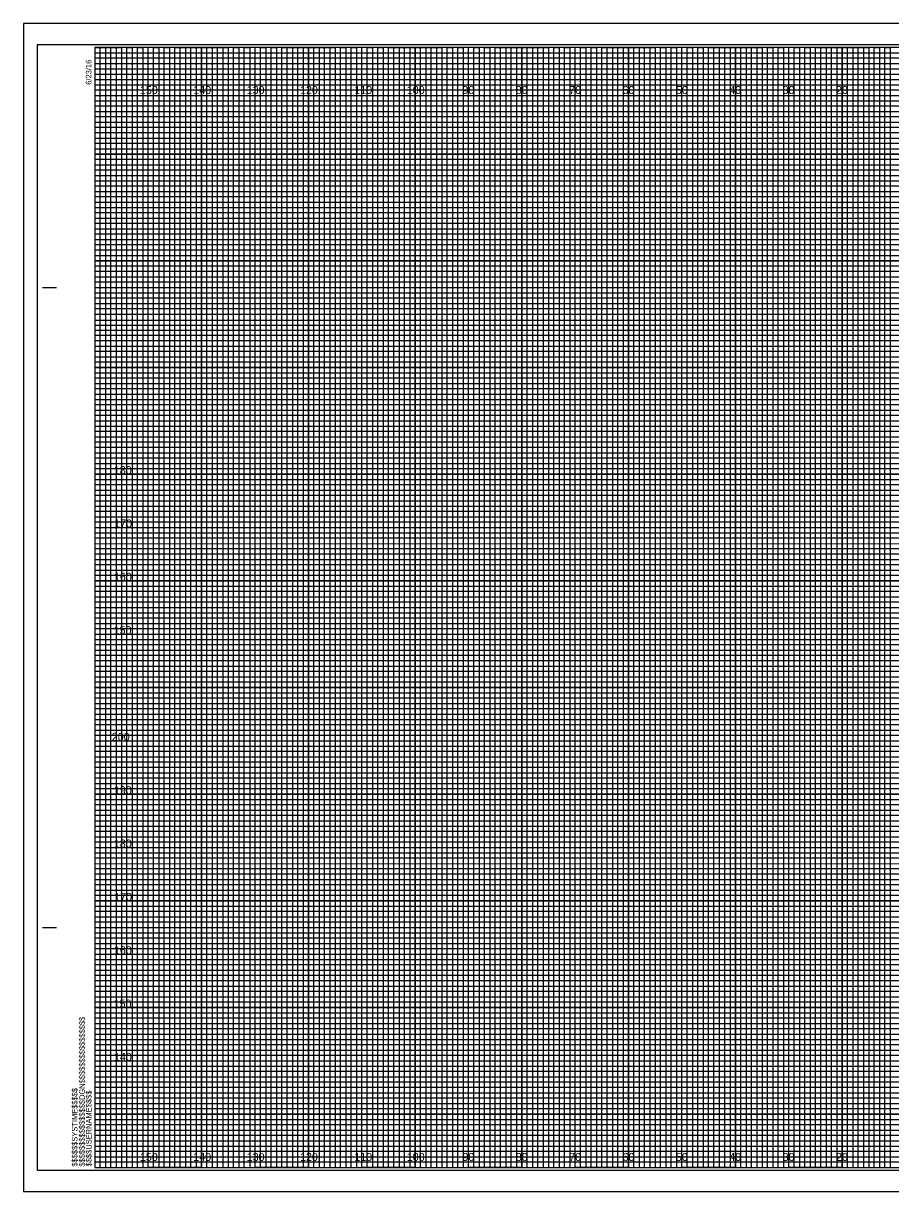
# Model space of a CAD drawing. Extents: x -13 to 323, y -5 to 4174.
# Drawn here: x -13.4 to 149.1, y 3295.5 to 3514.5 of the extents above; entities that cross this region are included whole.
import ezdxf

# ---------------------------------------------------------------- set-up
doc = ezdxf.new("R2010")
doc.units = 0
for name, color, linetype in [('Exist Cross Section Cell', 7, 'Continuous'), ('Exist XS Center Line Elevation Label', 7, 'Continuous'), ('Exist XS Ground Line', 7, 'Continuous'), ('Prop CMT Guardrail Graphics', 7, 'Continuous'), ('Prop CMT Pvmt Course 1', 7, 'Continuous'), ('Prop CMT Pvmt Course 2', 7, 'Continuous'), ('Prop CMT Pvmt Course 3', 7, 'Continuous'), ('Prop CMT Shld Paved Course 1', 7, 'Continuous'), ('Prop CMT Shld Paved Course 2', 7, 'Continuous'), ('Prop CMT Subgrade Earthwork', 7, 'Continuous'), ('Scratch_Level_0', 7, 'Continuous')]:
    doc.layers.add(name, color=color, linetype=linetype)

msp = doc.modelspace()

# ---------------------------------------------------------------- linework, layer by layer
at = {"layer": 'Exist XS Center Line Elevation Label'}
for points in [[(0, 3510), (5, 3510), (5, 3300), (15, 3300), (15, 3510), (25, 3510), (25, 3300), (35, 3300), (35, 3510), (45, 3510), (45, 3300), (55, 3300), (55, 3510), (65, 3510), (65, 3300), (75, 3300), (75, 3510), (85, 3510), (85, 3300), (95, 3300), (95, 3510), (105, 3510), (105, 3300), (115, 3300), (115, 3510), (125, 3510), (125, 3300), (135, 3300), (135, 3510), (145, 3510), (145, 3300), (155, 3300)], [(0, 3505), (275, 3505)], [(0, 3485), (320, 3485), (320, 3495), (0, 3495)], [(0, 3465), (320, 3465), (320, 3475), (0, 3475)], [(0, 3445), (320, 3445), (320, 3455), (0, 3455)], [(0, 3425), (320, 3425), (320, 3435), (0, 3435)], [(0, 3405), (320, 3405), (320, 3415), (0, 3415)], [(0, 3385), (320, 3385), (320, 3395), (0, 3395)], [(0, 3365), (320, 3365), (320, 3375), (0, 3375)], [(0, 3345), (320, 3345), (320, 3355), (0, 3355)], [(0, 3325), (320, 3325), (320, 3335), (0, 3335)], [(0, 3305), (320, 3305), (320, 3315), (0, 3315)]]:
    msp.add_lwpolyline(points, dxfattribs=at)
at = {"layer": 'Exist XS Ground Line'}
for p, q in [((10, 3510), (0, 3510)), ((10, 3300), (10, 3510)), ((30, 3510), (20, 3510)), ((20, 3510), (20, 3300)), ((30, 3300), (30, 3510)), ((50, 3510), (40, 3510)), ((40, 3510), (40, 3300)), ((50, 3300), (50, 3510)), ((70, 3510), (60, 3510)), ((60, 3510), (60, 3300)), ((70, 3300), (70, 3510)), ((90, 3510), (80, 3510)), ((80, 3510), (80, 3300)), ((90, 3300), (90, 3510)), ((110, 3510), (100, 3510)), ((100, 3510), (100, 3300)), ((110, 3300), (110, 3510)), ((130, 3510), (120, 3510)), ((120, 3510), (120, 3300)), ((130, 3300), (130, 3510)), ((150, 3510), (140, 3510)), ((140, 3510), (140, 3300)), ((20, 3300), (10, 3300)), ((40, 3300), (30, 3300)), ((60, 3300), (50, 3300)), ((80, 3300), (70, 3300)), ((100, 3300), (90, 3300)), ((120, 3300), (110, 3300)), ((140, 3300), (130, 3300))]:
    msp.add_line(p, q, dxfattribs=at)
for points in [[(0, 3500), (320, 3500), (320, 3490), (0, 3490)], [(0, 3480), (320, 3480), (320, 3470), (0, 3470)], [(0, 3460), (320, 3460), (320, 3450), (0, 3450)], [(0, 3440), (320, 3440), (320, 3430), (0, 3430)], [(0, 3420), (320, 3420), (320, 3410), (0, 3410)], [(0, 3400), (320, 3400), (320, 3390), (0, 3390)], [(0, 3380), (320, 3380), (320, 3370), (0, 3370)], [(0, 3360), (320, 3360), (320, 3350), (0, 3350)], [(0, 3340), (320, 3340), (320, 3330), (0, 3330)], [(0, 3320), (320, 3320), (320, 3310), (0, 3310)]]:
    msp.add_lwpolyline(points, dxfattribs=at)
at = {"layer": 'Prop CMT Pvmt Course 1'}
for p, q in [((323.3, 3514.5), (-13.4, 3514.5)), ((-13.4, 3514.5), (-13.4, 3295.5)), ((-13.4, 3295.5), (323.3, 3295.5))]:
    msp.add_line(p, q, dxfattribs=at)
at = {"layer": 'Prop CMT Pvmt Course 2'}
msp.add_lwpolyline([(-13.4, 3295.5), (323.3, 3295.5), (323.3, 3514.5), (-13.4, 3514.5)], close=True, dxfattribs=at)
at = {"layer": 'Prop CMT Pvmt Course 3'}
msp.add_lwpolyline([(-10.8, 3299.5), (322.4, 3299.5), (322.4, 3510.5), (-10.8, 3510.5)], close=True, dxfattribs=at)
at = {"layer": 'Prop CMT Shld Paved Course 1'}
for p, q in [((-9.8, 3465), (-7.3, 3465)), ((-9.7, 3465), (-7.2, 3465)), ((-9.8, 3345), (-7.3, 3345)), ((-9.7, 3345), (-7.2, 3345)), ((0, 3300), (0, 3300)), ((0, 3300), (0, 3300)), ((0, 3300), (0, 3300)), ((0, 3300), (0, 3300)), ((0, 3300), (0, 3300)), ((0, 3300), (0, 3300)), ((0, 3300), (0, 3300))]:
    msp.add_line(p, q, dxfattribs=at)
msp.add_lwpolyline([(320, 3510), (0, 3510), (0, 3300), (320, 3300)], close=True, dxfattribs=at)
at = {"layer": 'Prop CMT Shld Paved Course 2'}
for points in [[(0, 3300), (1, 3300), (1, 3510), (2, 3510), (2, 3300)], [(2, 3300), (3, 3300), (3, 3510), (4, 3510), (4, 3300)], [(5, 3300), (6, 3300), (6, 3510), (7, 3510), (7, 3300)], [(7, 3300), (8, 3300), (8, 3510), (9, 3510), (9, 3300)], [(10, 3300), (11, 3300), (11, 3510), (12, 3510), (12, 3300)], [(12, 3300), (13, 3300), (13, 3510), (14, 3510), (14, 3300)], [(15, 3300), (16, 3300), (16, 3510), (17, 3510), (17, 3300)], [(17, 3300), (18, 3300), (18, 3510), (19, 3510), (19, 3300)], [(20, 3300), (21, 3300), (21, 3510), (22, 3510), (22, 3300)], [(22, 3300), (23, 3300), (23, 3510), (24, 3510), (24, 3300)], [(25, 3300), (26, 3300), (26, 3510), (27, 3510), (27, 3300)], [(27, 3300), (28, 3300), (28, 3510), (29, 3510), (29, 3300)], [(30, 3300), (31, 3300), (31, 3510), (32, 3510), (32, 3300)], [(32, 3300), (33, 3300), (33, 3510), (34, 3510), (34, 3300)], [(35, 3300), (36, 3300), (36, 3510), (37, 3510), (37, 3300)], [(37, 3300), (38, 3300), (38, 3510), (39, 3510), (39, 3300)], [(40, 3300), (41, 3300), (41, 3510), (42, 3510), (42, 3300)], [(42, 3300), (43, 3300), (43, 3510), (44, 3510), (44, 3300)], [(45, 3300), (46, 3300), (46, 3510), (47, 3510), (47, 3300)], [(47, 3300), (48, 3300), (48, 3510), (49, 3510), (49, 3300)], [(50, 3300), (51, 3300), (51, 3510), (52, 3510), (52, 3300)], [(52, 3300), (53, 3300), (53, 3510), (54, 3510), (54, 3300)], [(55, 3300), (56, 3300), (56, 3510), (57, 3510), (57, 3300)], [(57, 3300), (58, 3300), (58, 3510), (59, 3510), (59, 3300)], [(60, 3300), (61, 3300), (61, 3510), (62, 3510), (62, 3300)], [(62, 3300), (63, 3300), (63, 3510), (64, 3510), (64, 3300)], [(65, 3300), (66, 3300), (66, 3510), (67, 3510), (67, 3300)], [(67, 3300), (68, 3300), (68, 3510), (69, 3510), (69, 3300)], [(70, 3300), (71, 3300), (71, 3510), (72, 3510), (72, 3300)], [(72, 3300), (73, 3300), (73, 3510), (74, 3510), (74, 3300)], [(75, 3300), (76, 3300), (76, 3510), (77, 3510), (77, 3300)], [(77, 3300), (78, 3300), (78, 3510), (79, 3510), (79, 3300)], [(80, 3300), (81, 3300), (81, 3510), (82, 3510), (82, 3300)], [(82, 3300), (83, 3300), (83, 3510), (84, 3510), (84, 3300)], [(85, 3300), (86, 3300), (86, 3510), (87, 3510), (87, 3300)], [(87, 3300), (88, 3300), (88, 3510), (89, 3510), (89, 3300)], [(90, 3300), (91, 3300), (91, 3510), (92, 3510), (92, 3300)], [(92, 3300), (93, 3300), (93, 3510), (94, 3510), (94, 3300)], [(95, 3300), (96, 3300), (96, 3510), (97, 3510), (97, 3300)], [(97, 3300), (98, 3300), (98, 3510), (99, 3510), (99, 3300)], [(100, 3300), (101, 3300), (101, 3510), (102, 3510), (102, 3300)], [(102, 3300), (103, 3300), (103, 3510), (104, 3510), (104, 3300)], [(105, 3300), (106, 3300), (106, 3510), (107, 3510), (107, 3300)], [(107, 3300), (108, 3300), (108, 3510), (109, 3510), (109, 3300)], [(110, 3300), (111, 3300), (111, 3510), (112, 3510), (112, 3300)], [(112, 3300), (113, 3300), (113, 3510), (114, 3510), (114, 3300)], [(115, 3300), (116, 3300), (116, 3510), (117, 3510), (117, 3300)], [(117, 3300), (118, 3300), (118, 3510), (119, 3510), (119, 3300)], [(120, 3300), (121, 3300), (121, 3510), (122, 3510), (122, 3300)], [(122, 3300), (123, 3300), (123, 3510), (124, 3510), (124, 3300)], [(125, 3300), (126, 3300), (126, 3510), (127, 3510), (127, 3300)], [(127, 3300), (128, 3300), (128, 3510), (129, 3510), (129, 3300)], [(130, 3300), (131, 3300), (131, 3510), (132, 3510), (132, 3300)], [(132, 3300), (133, 3300), (133, 3510), (134, 3510), (134, 3300)], [(135, 3300), (136, 3300), (136, 3510), (137, 3510), (137, 3300)], [(137, 3300), (138, 3300), (138, 3510), (139, 3510), (139, 3300)], [(140, 3300), (141, 3300), (141, 3510), (142, 3510), (142, 3300)], [(142, 3300), (143, 3300), (143, 3510), (144, 3510), (144, 3300)], [(145, 3300), (146, 3300), (146, 3510), (147, 3510), (147, 3300)], [(147, 3300), (148, 3300), (148, 3510), (149, 3510), (149, 3300)]]:
    msp.add_lwpolyline(points, dxfattribs=at)
at = {"layer": 'Prop CMT Subgrade Earthwork'}
for p, q in [((10, 3300), (10, 3510)), ((20, 3300), (20, 3510)), ((30, 3300), (30, 3510)), ((40, 3300), (40, 3510)), ((50, 3300), (50, 3510)), ((60, 3300), (60, 3510)), ((70, 3300), (70, 3510)), ((80, 3300), (80, 3510)), ((90, 3300), (90, 3510)), ((100, 3300), (100, 3510)), ((110, 3300), (110, 3510)), ((120, 3300), (120, 3510)), ((130, 3300), (130, 3510)), ((140, 3300), (140, 3510)), ((0, 3500), (320, 3500)), ((0, 3490), (320, 3490)), ((0, 3480), (320, 3480)), ((0, 3470), (320, 3470)), ((0, 3460), (320, 3460)), ((0, 3450), (320, 3450)), ((0, 3440), (320, 3440)), ((0, 3430), (320, 3430)), ((0, 3420), (320, 3420)), ((0, 3410), (320, 3410)), ((0, 3400), (320, 3400)), ((0, 3390), (320, 3390)), ((0, 3380), (320, 3380)), ((0, 3370), (320, 3370)), ((0, 3360), (320, 3360)), ((0, 3350), (320, 3350)), ((0, 3340), (320, 3340)), ((0, 3330), (320, 3330)), ((0, 3320), (320, 3320)), ((0, 3310), (320, 3310))]:
    msp.add_line(p, q, dxfattribs=at)
at = {"layer": 'Scratch_Level_0'}
for p, q in [((0, 3509), (260, 3509)), ((260, 3507.98), (0, 3507.98)), ((0, 3507.98), (0, 3507)), ((0, 3507), (260, 3507)), ((260, 3505.89), (0, 3505.89)), ((0, 3505.89), (0, 3504)), ((0, 3504), (320, 3504))]:
    msp.add_line(p, q, dxfattribs=at)
for points in [[(0, 3503), (270, 3503), (320, 3503), (320, 3502), (0, 3502)], [(0, 3501), (320, 3501), (320, 3499), (0, 3499)], [(0, 3498), (320, 3498), (320, 3497), (0, 3496.98)], [(0, 3496), (320, 3496), (320, 3494), (0, 3494)], [(0, 3493), (320, 3493), (320, 3492), (0, 3492)], [(0, 3491), (320, 3491), (320, 3489), (0, 3489)], [(0, 3488), (320, 3488), (320, 3487), (0, 3487)], [(0, 3486), (320, 3486), (320, 3484), (0, 3484)], [(0, 3483), (320, 3483), (320, 3482), (0, 3482)], [(0, 3481), (320, 3481), (320, 3479), (0, 3479)], [(0, 3478), (320, 3478), (320, 3477), (0, 3477)], [(0, 3476), (320, 3476), (320, 3473.95), (320, 3473), (320, 3472), (0, 3472)], [(0, 3474), (320, 3474), (320, 3473), (0, 3473)], [(0, 3471), (320, 3471), (320, 3469), (0, 3469.03)], [(0, 3469.03), (320, 3469), (320, 3468), (0, 3468)], [(0, 3467), (320, 3467), (320, 3466), (0, 3466)], [(0, 3464), (320, 3464), (320, 3463), (0, 3463)], [(0, 3462), (320, 3462), (320, 3461), (0, 3461)], [(-0.07, 3458.89), (320, 3458.89), (320, 3457.88), (-0.07, 3457.88)], [(0, 3457), (320, 3457), (320, 3456), (0, 3456)], [(0, 3454), (320, 3454), (320, 3453), (0, 3453)], [(0, 3452), (320, 3452), (320, 3451), (0, 3451)], [(0, 3449), (320, 3449), (320, 3448), (0, 3448)], [(0, 3447), (320, 3447), (320, 3446), (0, 3446)], [(0, 3444), (320, 3444), (320, 3443), (0, 3443)], [(0, 3442), (320, 3442), (320, 3441), (0, 3441)], [(0, 3439), (320, 3439), (319.99, 3437.98), (0, 3438)], [(0, 3437), (320, 3437), (320, 3436), (0, 3436)], [(0, 3434), (320, 3434), (320, 3433), (0, 3433)], [(0, 3432), (320, 3432), (320, 3431), (0, 3431)], [(0, 3429), (320, 3429), (320, 3428), (0, 3428)], [(0, 3427), (320, 3427), (320, 3426), (0, 3426)], [(0, 3424), (320, 3424), (320, 3423), (0, 3423)], [(0, 3422), (320, 3422), (320, 3421), (0, 3421)], [(0, 3419), (320, 3419), (320, 3418), (0, 3418)], [(0, 3416.99), (320.07, 3416.91), (320, 3416), (0, 3416)], [(0, 3414), (320, 3414), (320, 3413), (0, 3413)], [(0, 3412), (320, 3412), (320, 3411), (0, 3411)], [(0, 3409), (320, 3409), (320, 3408), (0, 3408)], [(0, 3407), (320, 3407), (320, 3406), (0, 3406)], [(0, 3404), (320, 3404), (320, 3403), (0, 3403)], [(0, 3402), (320, 3402), (320, 3401), (0, 3401)], [(0, 3399), (320, 3399), (320, 3398), (0, 3398)], [(0, 3397), (320, 3397), (320, 3396), (0, 3396)], [(0, 3394), (320, 3394), (320, 3393), (0, 3393)], [(0, 3392), (320, 3392), (320, 3391), (0, 3391)], [(0, 3389), (320, 3389), (320, 3388), (0, 3388)], [(0, 3387), (320, 3387), (320, 3386), (0, 3386)], [(0, 3384), (320, 3384), (320, 3383), (0, 3383)], [(0, 3382), (320, 3382), (320, 3381), (0, 3381)], [(0, 3379), (320, 3379), (319.99, 3377.98), (0, 3378)], [(0, 3377), (320, 3377), (320, 3376), (0, 3376)], [(0, 3374), (320, 3374), (320, 3373), (0, 3373)], [(0, 3372), (320, 3372), (320, 3371), (0, 3371)], [(0, 3369), (320, 3369), (320, 3368), (0, 3368)], [(0, 3367), (320, 3367), (320, 3366), (0, 3366)], [(0, 3364), (320, 3364), (320, 3363), (0, 3363)], [(0, 3362), (320, 3362), (320, 3361), (0, 3361)], [(0, 3359), (320, 3359), (320, 3358), (0, 3358)], [(0, 3356.99), (320.07, 3356.91), (320, 3356), (0, 3356)], [(0, 3354), (320, 3354), (320, 3353), (0, 3353)], [(0, 3352), (320, 3352), (320, 3351), (0, 3351)], [(0, 3349), (320, 3349), (320, 3348), (0, 3348)], [(0, 3347), (320, 3347), (320, 3346), (0, 3346)], [(0, 3344), (320, 3344), (320, 3343), (0, 3343)], [(0, 3342), (320, 3342), (320, 3341), (0, 3341)], [(0, 3339), (320, 3339), (320, 3338), (0, 3338)], [(0, 3337), (320, 3337), (320, 3336), (0, 3336)], [(0, 3334), (320, 3334), (320, 3333), (0, 3333)], [(0, 3332), (320, 3332), (320, 3331), (0, 3331)], [(0, 3329), (320, 3329), (320, 3328), (0, 3328)], [(0, 3327), (320, 3327), (320, 3326), (0, 3326)], [(0, 3324), (320, 3324), (320, 3323), (0, 3323)], [(0, 3322), (320, 3322), (320, 3321), (0, 3321)], [(0, 3319), (320, 3319), (320, 3318), (0, 3318)], [(0, 3317), (320, 3317), (320, 3316), (0, 3316)], [(0, 3314), (320, 3314), (320, 3313), (0, 3313)], [(0, 3312), (320, 3312), (320, 3311), (0, 3311)], [(0, 3309), (320, 3309), (320, 3308), (0, 3308)], [(0, 3307), (320, 3307), (320, 3306), (0, 3306)], [(0, 3304), (320, 3304), (320, 3303), (0, 3303)], [(0, 3302), (320, 3302), (320, 3301), (0, 3301)]]:
    msp.add_lwpolyline(points, dxfattribs=at)

# ---------------------------------------------------------------- texts
at = {"layer": 'Exist Cross Section Cell'}
for s, p in [('150', (8.44, 3501.25)), ('140', (18.44, 3501.25)), ('130', (28.44, 3501.25)), ('120', (38.44, 3501.25)), ('110', (48.62, 3501.25)), ('100', (58.44, 3501.25)), ('90', (68.86, 3501.25)), ('80', (78.86, 3501.25)), ('70', (88.86, 3501.25)), ('60', (98.86, 3501.25)), ('50', (108.86, 3501.25)), ('40', (118.86, 3501.25)), ('30', (128.86, 3501.25)), ('20', (138.86, 3501.25)), ('150', (8.44, 3301.25)), ('140', (18.44, 3301.25)), ('130', (28.44, 3301.25)), ('120', (38.44, 3301.25)), ('110', (48.62, 3301.25)), ('100', (58.44, 3301.25)), ('90', (68.86, 3301.25)), ('80', (78.86, 3301.25)), ('70', (88.86, 3301.25)), ('60', (98.86, 3301.25)), ('50', (108.86, 3301.25)), ('40', (118.86, 3301.25)), ('30', (128.86, 3301.25)), ('20', (138.86, 3301.25))]:
    msp.add_text(s, height=1.5, dxfattribs=at).set_placement(p)
at = {"layer": 'Prop CMT Guardrail Graphics'}
for s, p in [('180', (3.55, 3430)), ('170', (3.61, 3420)), ('160', (3.57, 3410)), ('150', (3.52, 3400)), ('200', (3.17, 3380)), ('190', (3.57, 3370)), ('180', (3.55, 3360)), ('170', (3.61, 3350)), ('160', (3.57, 3340)), ('150', (3.52, 3330)), ('140', (3.57, 3320))]:
    msp.add_text(s, height=1.5, dxfattribs=at).set_placement(p)
at = {"layer": 'Prop CMT Shld Paved Course 1'}
for s, p in [('6/23/16', (-0.65, 3503)), ('$$$$$$$$$$$$$$$$DGN$$$$$$$$$$$$$$$$', (-1.88, 3300.18)), ('$$$$$$SYSTIME$$$$$', (-3.26, 3300.18)), ('$$$$USERNAME$$$$', (-0.62, 3300.23))]:
    msp.add_text(s, height=1.05, rotation=90, dxfattribs=at).set_placement(p)

doc.saveas('drawing.dxf')
